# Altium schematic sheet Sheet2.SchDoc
size A1
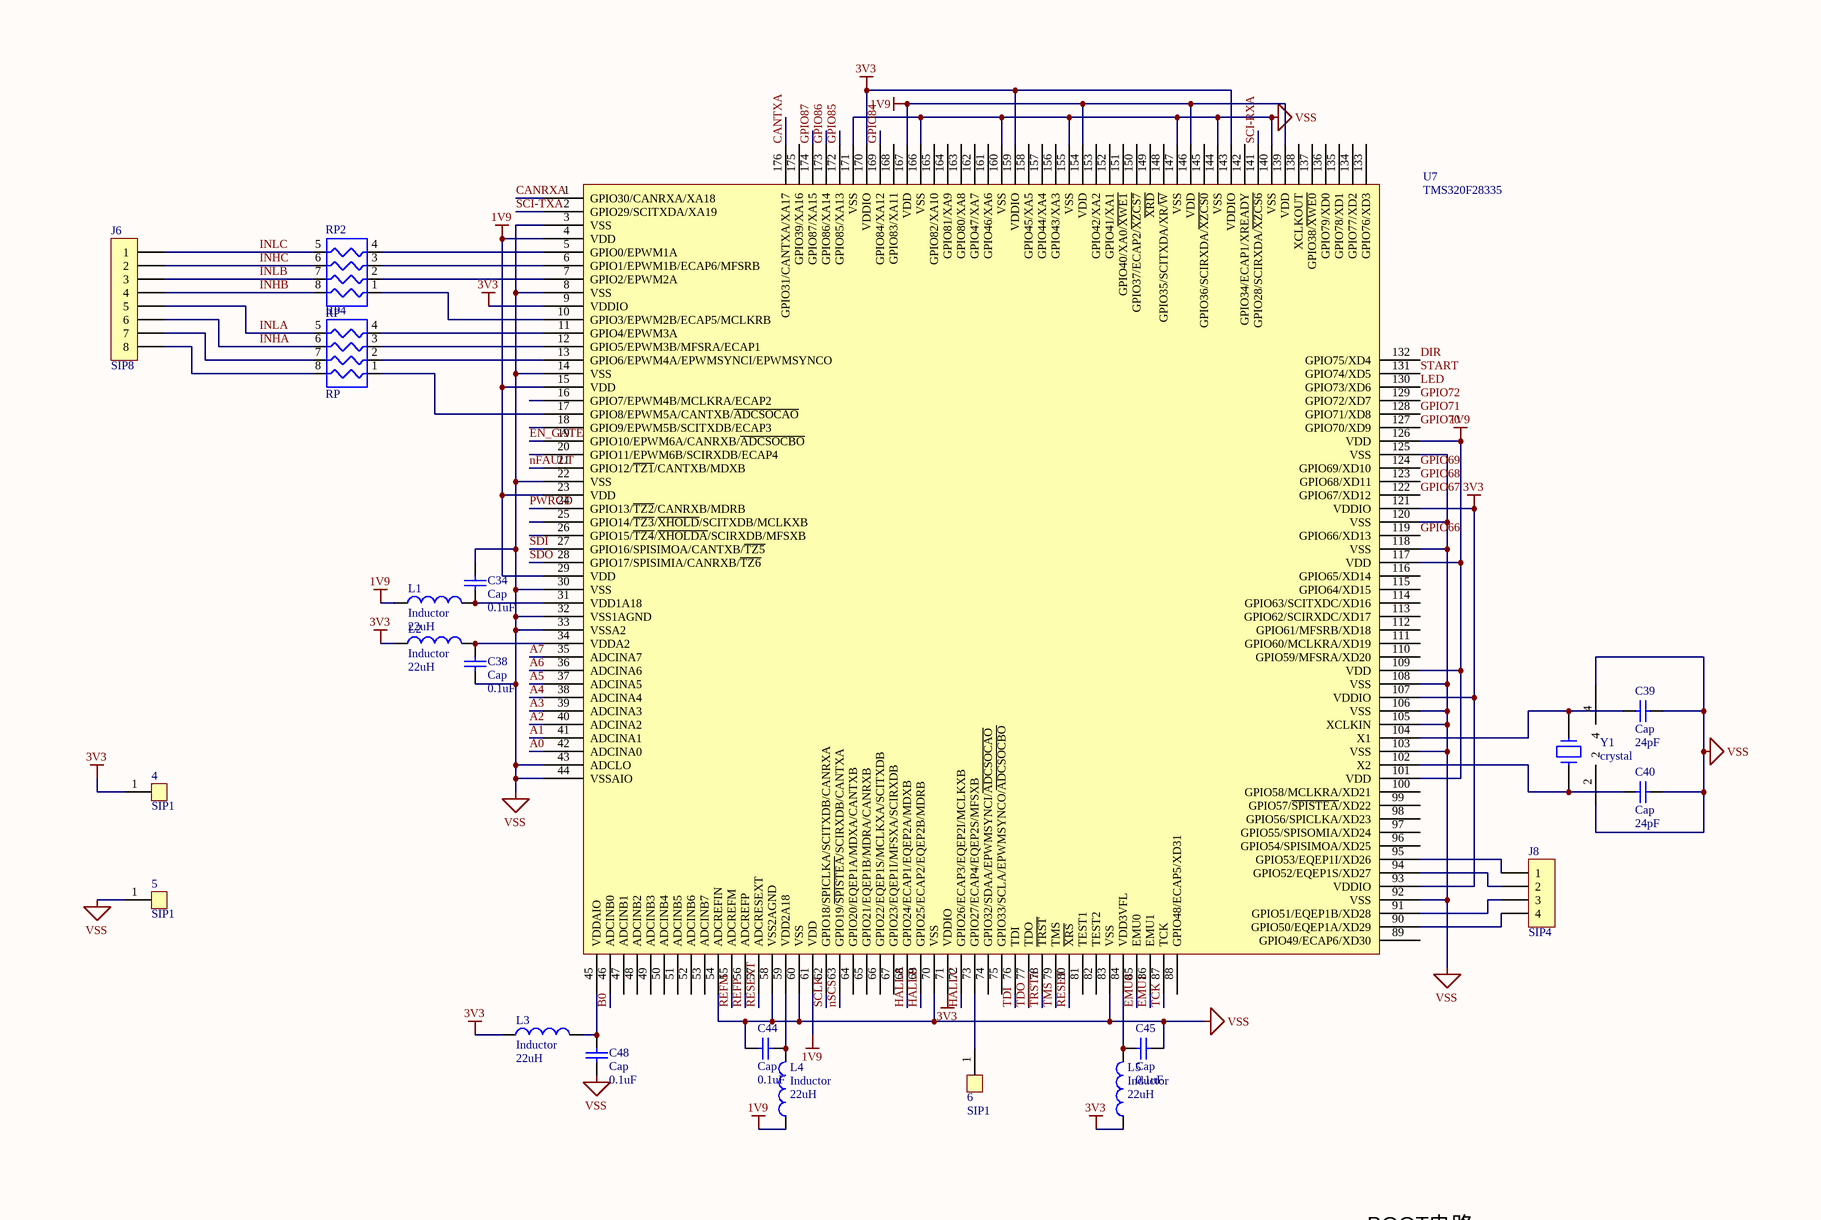
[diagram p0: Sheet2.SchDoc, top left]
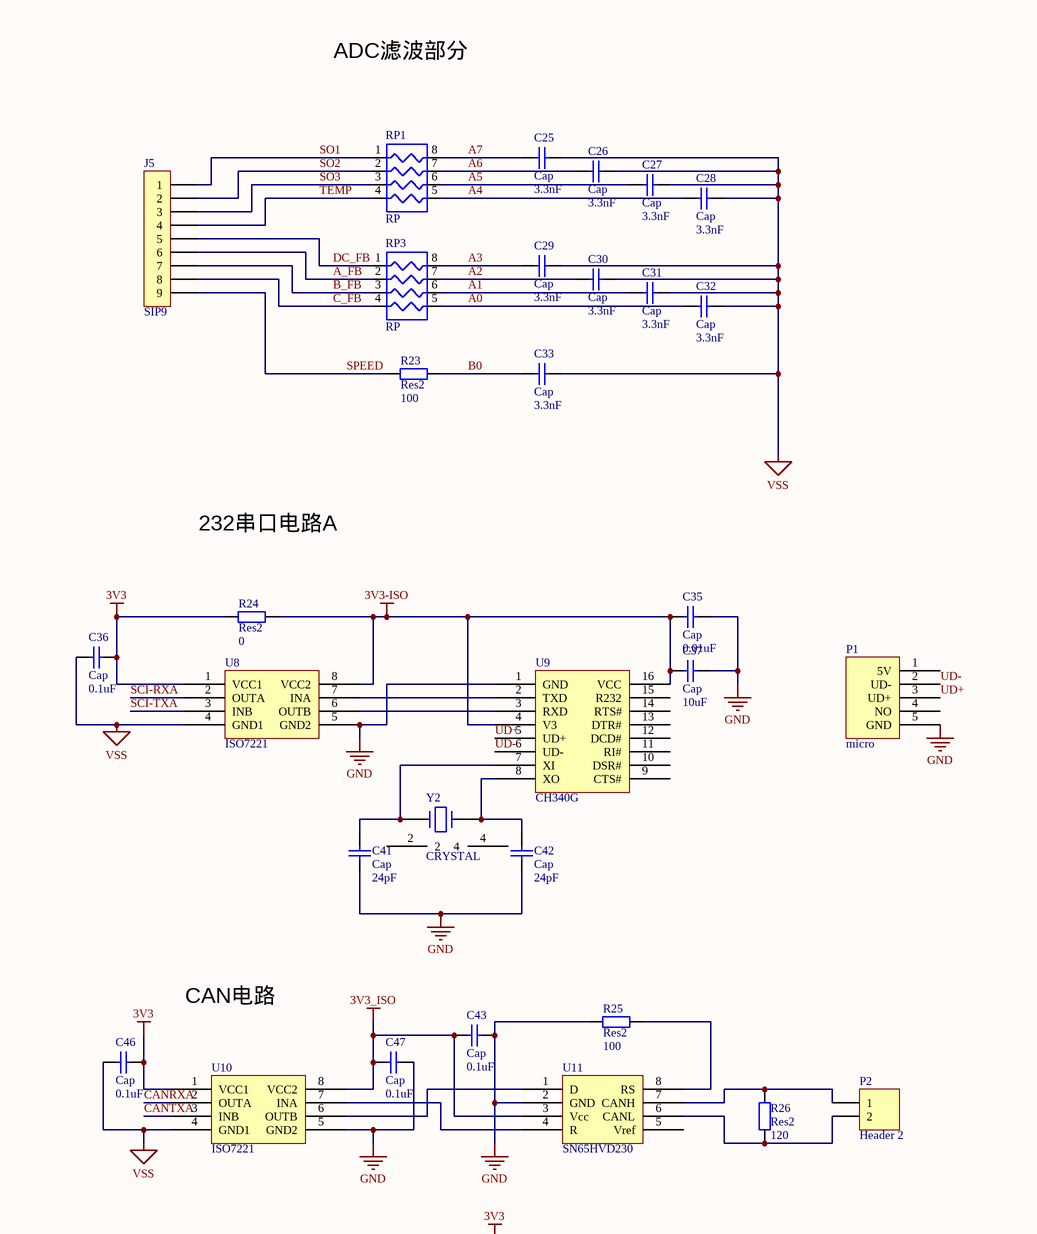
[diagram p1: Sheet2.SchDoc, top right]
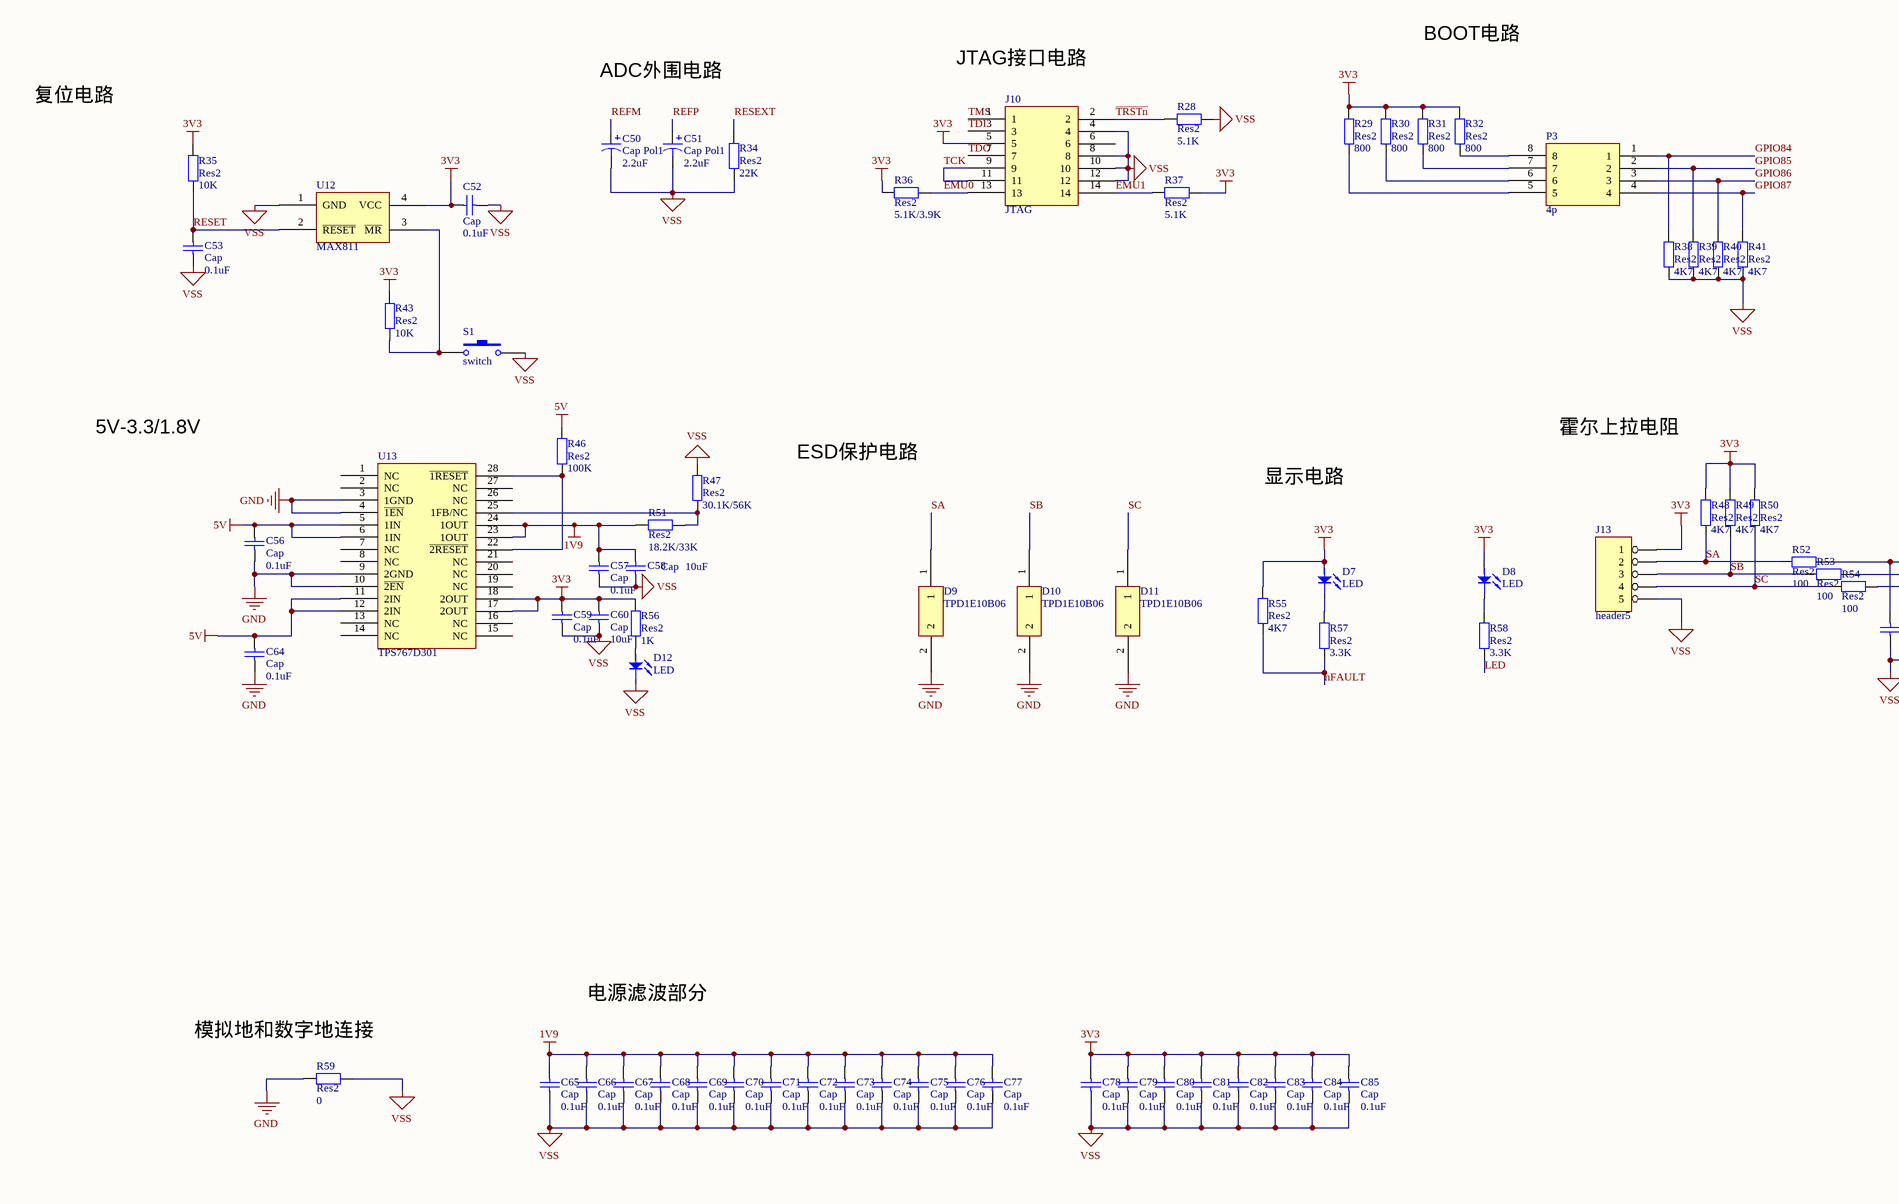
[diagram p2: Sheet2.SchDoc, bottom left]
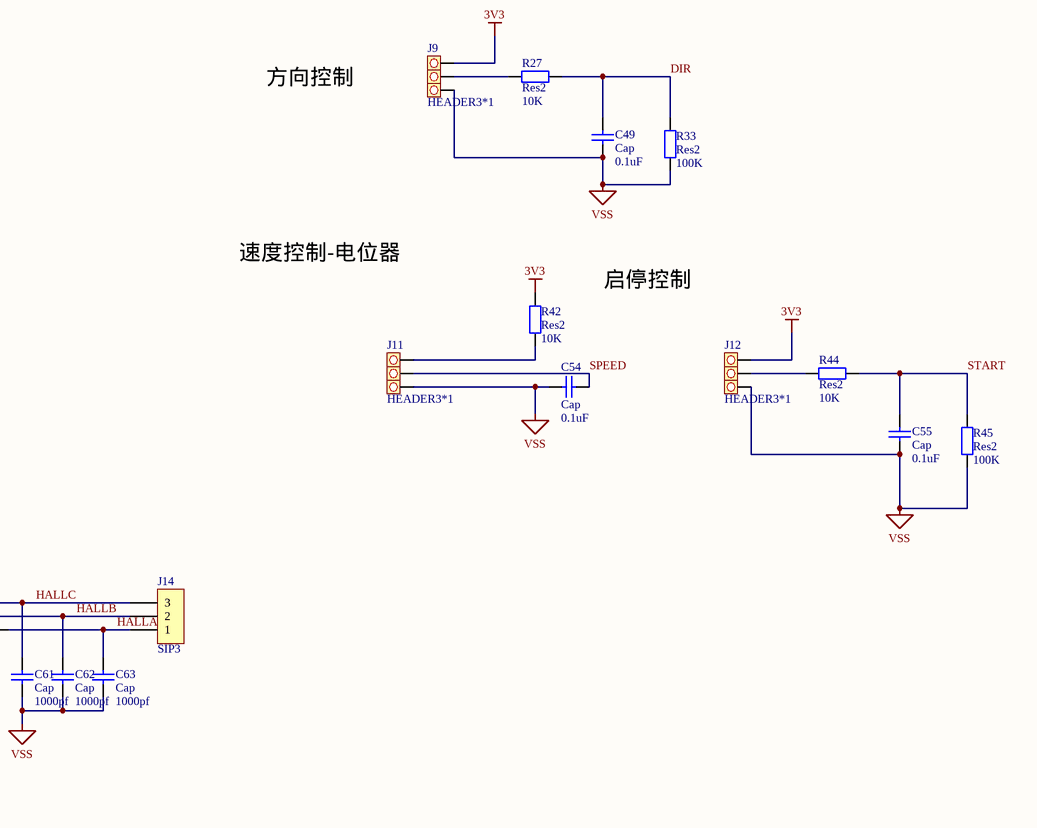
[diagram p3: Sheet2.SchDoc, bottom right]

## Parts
4  SIP1  [sip-1]
5  SIP1  [sip-1]
6  SIP1  [sip-1]
C25  Cap  value 3.3nF  [0805]
C26  Cap  value 3.3nF  [0805]
C27  Cap  value 3.3nF  [0805]
C28  Cap  value 3.3nF  [0805]
C29  Cap  value 3.3nF  [0805]
C30  Cap  value 3.3nF  [0805]
C31  Cap  value 3.3nF  [0805]
C32  Cap  value 3.3nF  [0805]
C33  Cap  value 3.3nF  [0805]
C34  Cap  value 0.1uF  [0805]
C35  Cap  value 0.01uF  [0805]
C36  Cap  value 0.1uF  [0805]
C37  Cap  value 10uF  [0805]
C38  Cap  value 0.1uF  [0805]
C39  Cap  value 24pF  [0603]
C40  Cap  value 24pF  [0603R]
C41  Cap  value 24pF  [0603]
C42  Cap  value 24pF  [0603]
C43  Cap  value 0.1uF  [0805]
C44  Cap  value 0.1uF  [0805]
C45  Cap  value 0.1uF  [0805]
C46  Cap  value 0.1uF  [0805]
C47  Cap  value 0.1uF  [0805]
C48  Cap  value 0.1uF  [0805]
C49  Cap  value 0.1uF  [0805]
C50  Cap Pol1  value 2.2uF  [0805]
C51  Cap Pol1  value 2.2uF  [0805]
C52  Cap  value 0.1uF  [0805]
C53  Cap  value 0.1uF  [0805]
C54  Cap  value 0.1uF  [0805]
C55  Cap  value 0.1uF  [0805]
C56  Cap  value 0.1uF  [0805]
C57  Cap  value 0.1uF  [0805]
C58  Cap  value 10uF  [0805]
C59  Cap  value 0.1uF  [0805]
C60  Cap  value 10uF  [0805]
C61  Cap  value 1000pf  [0805]
C62  Cap  value 1000pf  [0805]
C63  Cap  value 1000pf  [0805]
C64  Cap  value 0.1uF  [0805]
C65  Cap  value 0.1uF  [0805]
C66  Cap  value 0.1uF  [0805]
C67  Cap  value 0.1uF  [0805]
C68  Cap  value 0.1uF  [0805]
C69  Cap  value 0.1uF  [0805]
C70  Cap  value 0.1uF  [0805]
C71  Cap  value 0.1uF  [0805]
C72  Cap  value 0.1uF  [0805]
C73  Cap  value 0.1uF  [0805]
C74  Cap  value 0.1uF  [0805]
C75  Cap  value 0.1uF  [0805]
C76  Cap  value 0.1uF  [0805]
C77  Cap  value 0.1uF  [0805]
C78  Cap  value 0.1uF  [0805]
C79  Cap  value 0.1uF  [0805]
C80  Cap  value 0.1uF  [0805]
C81  Cap  value 0.1uF  [0805]
C82  Cap  value 0.1uF  [0805]
C83  Cap  value 0.1uF  [0805]
C84  Cap  value 0.1uF  [0805]
C85  Cap  value 0.1uF  [0805]
D7  LED  [0805]
D8  LED  [0805]
D9  TPD1E10B06  [0402]
D10  TPD1E10B06  [0402]
D11  TPD1E10B06  [0402]
D12  LED  [0805]
J5  SIP9  [SIP9-2.54]
J6  SIP8  [SIP8-2.54]
J8  SIP4  [SIP4-2.0]
J9  HEADER3*1  [zisuo]
J10  JTAG  [JTAG-14]
J11  HEADER3*1  [5.0J-3]
J12  HEADER3*1  [zisuo]
J13  header5  [5.0J-5]
J14  SIP3  [SIP3-2.54]
L1  Inductor  value 22uH  [0805]
L2  Inductor  value 22uH  [0805]
L3  Inductor  value 22uH  [0805]
L4  Inductor  value 22uH  [0805]
L5  Inductor  value 22uH  [0805]
P1  micro  [micro]
P2  Header 2  [5.0J-2]
P3  4p  [4P]
R23  Res2  value 100  [0805]
R24  Res2  value 0  [0805]
R25  Res2  value 100  [0805]
R26  Res2  value 120  [0805]
R27  Res2  value 10K  [0805]
R28  Res2  value 5.1K  [0805]
R29  Res2  value 800  [0805]
R30  Res2  value 800  [0805]
R31  Res2  value 800  [0805]
R32  Res2  value 800  [0805]
R33  Res2  value 100K  [0805]
R34  Res2  value 22K  [0805]
R35  Res2  value 10K  [0805]
R36  Res2  value 5.1K/3.9K  [0805]
R37  Res2  value 5.1K  [0805]
R38  Res2  value 4K7  [0805]
R39  Res2  value 4K7  [0805]
R40  Res2  value 4K7  [0805]
R41  Res2  value 4K7  [0805]
R42  Res2  value 10K  [0805]
R43  Res2  value 10K  [0805]
R44  Res2  value 10K  [0805]
R45  Res2  value 100K  [0805]
R46  Res2  value 100K  [0805]
R47  Res2  value 30.1K/56K  [0805]
R48  Res2  value 4K7  [0805]
R49  Res2  value 4K7  [0805]
R50  Res2  value 4K7  [0805]
R51  Res2  value 18.2K/33K  [0805]
R52  Res2  value 100  [0805]
R53  Res2  value 100  [0805]
R54  Res2  value 100  [0805]
R55  Res2  value 4K7  [0805]
R56  Res2  value 1K  [0805]
R57  Res2  value 3.3K  [0805]
R58  Res2  value 3.3K  [0805]
R59  Res2  value 0  [0805]
RP1  RP  [8P4R]
RP2  RP  [8P4R]
RP3  RP  [8P4R]
RP4  RP  [8P4R]
S1  switch  [switch - duplicate]
U7  TMS320F28335  [PTP]
U8  ISO7221  [SO-8]
U9  CH340G  [SOP16]
U10  ISO7221  [SO-8]
U11  SN65HVD230  [SO-8]
U12  MAX811  [SOT143]
U13  TPS767D301  [TPS767]
Y1  crystal  [5032]
Y2  CRYSTAL  [49SMD]

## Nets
1V9: C57.1 C58.2 C65.1 C66.2 C67.2 C68.1 C69.2 C70.2 C71.2 C72.2 C73.2 C74.2 C75.2 C76.2 C77.2 L1.1 L4.1 R51.1 U7.4(VDD) U7.15(VDD) U7.23(VDD) U7.29(VDD) U7.61(VDD) U7.101(VDD) U7.109(VDD) U7.117(VDD) U7.126(VDD) U7.139(VDD) U7.146(VDD) U7.154(VDD) U7.167(VDD) U13.23(1OUT) U13.24(1OUT)
3V3: 4.1 C36.2 C46.2 C52.1 C59.2 C60.2 C78.2 C79.2 C80.2 C81.2 C82.2 C83.2 C84.2 C85.2 D7.A D8.A J9.3 J10.5 J12.3 J13.1 L2.1 L3.1 L5.1 R24.1 R29.2 R30.2 R31.2 R32.2 R35.2 R36.1 R37.2 R42.2 R43.2 R48.2 R49.2 R50.2 R55.2 R56.2 U7.9(VDDIO) U7.71(VDDIO) U7.93(VDDIO) U7.107(VDDIO) U7.121(VDDIO) U7.143(VDDIO) U7.159(VDDIO) U7.170(VDDIO) U8.1(VCC1) U10.1(VCC1) U12.4(VCC) U13.17(2OUT) U13.18(2OUT)
3V3-ISO: C35.1 C37.1 R24.2 U8.8(VCC2) U9.4(V3) U9.16(VCC)
3V3_ISO: C43.1 C47.1 U10.8(VCC2) U11.3(Vcc)
5V: C56.2 C64.2 R46.2 U13.5(1IN) U13.6(1IN) U13.11(2IN) U13.12(2IN)
GND: C35.2 C37.2 C41.1 C42.1 C43.2 C47.2 C56.1 C64.1 D9.2 D10.2 D11.2 P1.5(GND) R25.1 R59.1 U8.5(GND2) U9.1(GND) U10.5(GND2) U11.2(GND) U13.3(1GND) U13.4(~{1EN}) U13.9(2GND) U13.10(~{2EN})
VSS: 5.1 C25.1 C26.1 C27.2 C28.1 C29.1 C30.1 C31.1 C32.1 C33.1 C34.2 C36.1 C38.1 C39.2 C40.2 C44.1 C45.2 C46.1 C48.1 C49.1 C50.2 C51.2 C52.2 C53.1 C54.1 C55.1 C57.2 C58.1 C59.1 C60.1 C61.1 C62.1 C63.1 C65.2 C66.1 C67.1 C68.2 C69.1 C70.1 C71.1 C72.1 C73.1 C74.1 C75.1 C76.1 C77.1 C78.1 C79.1 C80.1 C81.1 C82.1 C83.1 C84.1 C85.1 D12.K J9.1 J10.4 J10.8 J10.10 J10.12 J11.1 J12.1 J13.5 R28.2 R33.1 R34.1 R38.1 R39.1 R40.1 R41.1 R45.1 R47.1 R59.2 S1.2 U7.3(VSS) U7.8(VSS) U7.14(VSS) U7.22(VSS) U7.30(VSS) U7.32(VSS1AGND) U7.33(VSSA2) U7.43(ADCLO) U7.44(VSSAIO) U7.54(ADCREFIN) U7.58(VSS2AGND) U7.60(VSS) U7.70(VSS) U7.83(VSS) U7.92(VSS) U7.103(VSS) U7.105(XCLKIN) U7.106(VSS) U7.108(VSS) U7.118(VSS) U7.120(VSS) U7.125(VSS) U7.140(VSS) U7.144(VSS) U7.147(VSS) U7.155(VSS) U7.160(VSS) U7.166(VSS) U7.171(VSS) U8.4(GND1) U10.4(GND1) U12.1(GND) Y1.2 Y1.4
A0: C32.2 RP3.5 U7.42(ADCINA0)
A1: C31.2 RP3.6 U7.41(ADCINA1)
A2: C30.2 RP3.7 U7.40(ADCINA2)
A3: C29.2 RP3.8 U7.39(ADCINA3)
A4: C28.2 RP1.5 U7.38(ADCINA4)
A5: C27.1 RP1.6 U7.37(ADCINA5)
A6: C26.2 RP1.7 U7.36(ADCINA6)
A7: C25.2 RP1.8 U7.35(ADCINA7)
A_FB: J5.6 RP3.2
B0: C33.2 R23.2 U7.46(ADCINB0)
B_FB: J5.7 RP3.3
C_FB: J5.8 RP3.4
CANRXA: U7.1(GPIO30/CANRXA/XA18) U10.2(OUTA)
CANTXA: U7.176(GPIO31/CANTXA/XA17) U10.3(INB)
DC_FB: J5.5 RP3.1
DIR: C49.2 R27.2 R33.2 U7.132(GPIO75/XD4)
EMU0: J10.13 R36.2 U7.85(EMU0)
EMU1: J10.14 R37.1 U7.86(EMU1)
EN_GATE: U7.19(GPIO10/EPWM6A/CANRXB/~{ADCSOCBO})
GPIO66: U7.119(GPIO66/XD13)
GPIO67: U7.122(GPIO67/XD12)
GPIO68: U7.123(GPIO68/XD11)
GPIO69: U7.124(GPIO69/XD10)
GPIO70: U7.127(GPIO70/XD9)
GPIO71: U7.128(GPIO71/XD8)
GPIO72: U7.129(GPIO72/XD7)
GPIO84: P3.1 R38.2 U7.169(GPIO84/XA12)
GPIO85: P3.2 R39.2 U7.172(GPIO85/XA13)
GPIO86: P3.3 R40.2 U7.173(GPIO86/XA14)
GPIO87: P3.4 R41.2 U7.174(GPIO87/XA15)
HALLA: C63.2 J14.1 R54.2 U7.68(GPIO24/ECAP1/EQEP2A/MDXB)
HALLB: C62.2 J14.2 R53.2 U7.69(GPIO25/ECAP2/EQEP2B/MDRB)
HALLC: C61.2 J14.3 R52.2 U7.72(GPIO26/ECAP3/EQEP2I/MCLKXB)
INHA: J6.6 RP4.6
INHB: J6.4 RP2.8
INHC: J6.2 RP2.6
INLA: J6.5 RP4.5
INLB: J6.3 RP2.7
INLC: J6.1 RP2.5
LED: R58.1 U7.130(GPIO73/XD6)
nFAULT: R55.1 R57.1 U7.21(GPIO12/~{TZ1}/CANTXB/MDXB)
nSCS: U7.63(GPIO19/~{SPISTEA}/SCIRXDB/CANTXA)
PWRGD: U7.24(GPIO13/~{TZ2}/CANRXB/MDRB)
REFM: C50.1 U7.55(ADCREFM)
REFP: C51.1 U7.56(ADCREFP)
RESET: C53.2 R35.1 U7.80(~{XRS}) U12.2(~{RESET})
RESEXT: R34.2 U7.57(ADCRESEXT)
SA: D9.1 J13.2 R48.1 R52.1
SB: D10.1 J13.3 R49.1 R53.1
SC: D11.1 J13.4 R50.1 R54.1
SCI-RXA: U7.141(GPIO28/SCIRXDA/~{XZCS6}) U8.2(OUTA)
SCI-TXA: U7.2(GPIO29/SCITXDA/XA19) U8.3(INB)
SCLK: U7.62(GPIO18/SPICLKA/SCITXDB/CANRXA)
SDI: U7.27(GPIO16/SPISIMOA/CANTXB/~{TZ5})
SDO: U7.28(GPIO17/SPISIMIA/CANRXB/~{TZ6})
SO1: J5.1 RP1.1
SO2: J5.2 RP1.2
SO3: J5.3 RP1.3
SPEED: C54.2 J5.9 J11.2 R23.1
START: C55.2 R44.2 R45.2 U7.131(GPIO74/XD5)
~{TRSTn}: J10.2 R28.1 U7.78(~{TRST})
TCK: J10.9 J10.11 U7.87(TCK)
TDI: J10.3 U7.76(TDI)
TDO: J10.7 U7.77(TDO)
TEMP: J5.4 RP1.4
TMS: J10.1 U7.79(TMS)
UD+: P1.3(UD+) U9.5(UD+)
UD-: P1.2(UD-) U9.6(UD-)
Net6_1: 6.1 U7.73(GPIO27/ECAP4/EQEP2S/MFSXB)
NetC34_1: C34.1 L1.2 U7.31(VDD1A18)
NetC38_2: C38.2 L2.2 U7.34(VDDA2)
NetC39_1: C39.1 U7.104(X1) Y1.3
NetC40_1: C40.1 U7.102(X2) Y1.1
NetC41_2: C41.2 U9.7(XI) Y2.1
NetC42_2: C42.2 U9.8(XO) Y2.3
NetC44_2: C44.2 L4.2 U7.59(VDD2A18)
NetC45_1: C45.1 L5.2 U7.84(VDD3VFL)
NetC48_2: C48.2 L3.2 U7.45(VDDAIO)
NetD7_K: D7.K R57.2
NetD8_K: D8.K R58.2
NetD12_A: D12.A R56.1
NetJ6_7: J6.7 RP4.7
NetJ6_8: J6.8 RP4.8
NetJ8_1: J8.1 U7.95(GPIO53/EQEP1I/XD26)
NetJ8_2: J8.2 U7.94(GPIO52/EQEP1S/XD27)
NetJ8_3: J8.3 U7.91(GPIO51/EQEP1B/XD28)
NetJ8_4: J8.4 U7.90(GPIO50/EQEP1A/XD29)
NetJ9_2: J9.2 R27.1
NetJ11_3: J11.3 R42.1
NetJ12_2: J12.2 R44.1
NetP2_1: P2.1 R26.2 U11.7(CANH)
NetP2_2: P2.2 R26.1 U11.6(CANL)
NetP3_5: P3.5 R29.1
NetP3_6: P3.6 R30.1
NetP3_7: P3.7 R31.1
NetP3_8: P3.8 R32.1
NetR25_2: R25.2 U11.8(RS)
NetR43_1: R43.1 S1.1 U12.3(~{MR})
NetR46_1: R46.1 U13.22(~{2RESET}) U13.28(~{1RESET})
NetR47_2: R47.2 R51.2 U13.25(1FB/NC)
NetRP2_1: RP2.1 U7.10(GPIO3/EPWM2B/ECAP5/MCLKRB)
NetRP2_2: RP2.2 U7.7(GPIO2/EPWM2A)
NetRP2_3: RP2.3 U7.6(GPIO1/EPWM1B/ECAP6/MFSRB)
NetRP2_4: RP2.4 U7.5(GPIO0/EPWM1A)
NetRP4_1: RP4.1 U7.17(GPIO8/EPWM5A/CANTXB/~{ADCSOCAO})
NetRP4_2: RP4.2 U7.13(GPIO6/EPWM4A/EPWMSYNCI/EPWMSYNCO)
NetRP4_3: RP4.3 U7.12(GPIO5/EPWM3B/MFSRA/ECAP1)
NetRP4_4: RP4.4 U7.11(GPIO4/EPWM3A)
NetU8_6: U8.6(OUTB) U9.3(RXD)
NetU8_7: U8.7(INA) U9.2(TXD)
NetU10_6: U10.6(OUTB) U11.1(D)
NetU10_7: U10.7(INA) U11.4(R)

Not connected (* = marked no-connect by the designer): J10 6; P1 1(5V) 4(NO); U7 16(GPIO7/EPWM4B/MCLKRA/ECAP2) 18(GPIO9/EPWM5B/SCITXDB/ECAP3) 20(GPIO11/EPWM6B/SCIRXDB/ECAP4) 25(GPIO14/~{TZ3}/~{XHOLD}/SCITXDB/MCLKXB) 26(GPIO15/~{TZ4}/~{XHOLDA}/SCIRXDB/MFSXB) 47(ADCINB1) 48(ADCINB2) 49(ADCINB3) 50(ADCINB4) 51(ADCINB5) 52(ADCINB6) 53(ADCINB7) 64(GPIO20/EQEP1A/MDXA/CANTXB) 65(GPIO21/EQEP1B/MDRA/CANRXB) 66(GPIO22/EQEP1S/MCLKXA/SCITXDB) 67(GPIO23/EQEP1I/MFSXA/SCIRXDB) 74(GPIO32/SDAA/EPWMSYNCI/~{ADCSOCAO}) 75(GPIO33/SCLA/EPWMSYNCO/~{ADCSOCBO}) 81(TEST1) 82(TEST2) 88(GPIO48/ECAP5/XD31) 89(GPIO49/ECAP6/XD30) 96(GPIO54/SPISIMOA/XD25) 97(GPIO55/SPISOMIA/XD24) 98(GPIO56/SPICLKA/XD23) 99(GPIO57/~{SPISTEA}/XD22) 100(GPIO58/MCLKRA/XD21) 110(GPIO59/MFSRA/XD20) 111(GPIO60/MCLKRA/XD19) 112(GPIO61/MFSRB/XD18) 113(GPIO62/SCIRXDC/XD17) 114(GPIO63/SCITXDC/XD16) 115(GPIO64/XD15) 116(GPIO65/XD14) 133(GPIO76/XD3) 134(GPIO77/XD2) 135(GPIO78/XD1) 136(GPIO79/XD0) 137(GPIO38/~{XWE0}) 138(XCLKOUT) 142(GPIO34/ECAP1/XREADY) 145(GPIO36/SCIRXDA/~{XZCS0}) 148(GPIO35/SCITXDA/XR/~{W}) 149(~{XRD}) 150(GPIO37/ECAP2/~{XZCS7}) 151(GPIO40/XA0/~{XWE1}) 152(GPIO41/XA1) 153(GPIO42/XA2) 156(GPIO43/XA3) 157(GPIO44/XA4) 158(GPIO45/XA5) 161(GPIO46/XA6) 162(GPIO47/XA7) 163(GPIO80/XA8) 164(GPIO81/XA9) 165(GPIO82/XA10) 168(GPIO83/XA11) 175(GPIO39/XA16); U9 9(CTS#) 10(DSR#) 11(RI#) 12(DCD#) 13(DTR#) 14(RTS#) 15(R232); U11 5(Vref); U13 1(NC) 2(NC) 7(NC) 8(NC) 13(NC) 14(NC) 15(NC) 16(NC) 19(NC) 20(NC) 21(NC) 26(NC) 27(NC); Y2 2 4

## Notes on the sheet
- ADC滤波部分
- 232串口电路A
- CAN电路
- BOOT电路
- 复位电路
- ADC外围电路
- JTAG接口电路
- (near J9) 方向控制
- 速度控制-电位器
- 启停控制
- 5V-3.3/1.8V
- ESD保护电路
- 霍尔上拉电阻
- 显示电路
- 电源滤波部分
- (near R59) 模拟地和数字地连接

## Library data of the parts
4-6 = SIP1: Variable Resistor; Set Position: 0.5
C25-C49 C52-C85 = Cap: Capacitor
C50 C51 = Cap Pol1: Polarized Capacitor (Radial)
D7 D8 D12 = LED: pin to pad: A>1 K>2
J5 = SIP9: jointbar
J6 = SIP8: jointbar
J8 = SIP4: jointbar
J14 = SIP3: jointbar
L1-L5 = Inductor: Code_IEC: 1005
P2 = Header 2: Header, 2-Pin
R23-R59 = Res2: Resistor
